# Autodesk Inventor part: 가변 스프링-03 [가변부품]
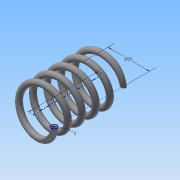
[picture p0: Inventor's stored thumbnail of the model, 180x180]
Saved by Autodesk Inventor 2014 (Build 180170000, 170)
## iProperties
Created: 2015-09
Part Number: 가변 스프링-03 [가변부품]
Material: 강철, 탄소
Document SubType Name: Modeling
Designer: study
Density: 7.87 g/cm^3
Appearance: 반연마
Mass: 18.8111 g
Surface Area: 32.4633 cm^2
Volume: 2.39023 cm^3
Author: study
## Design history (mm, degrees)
sketch "스케치1"
  geometry: L1 (0, 0)-(11, 0); L2 (11, 0)-(11, 28.893); L3 (11, 28.893)-(0, 28.893); L4 (0, 28.893)-(0, 0); C1 r 1.5 at (11, 0)
  constraints: 8 end point, 2 parallel, 1 centre point, 1 coincident, 1 horizontal, 1 perpendicular
  dimensions: "d0" = 22 diameter of L2.end L4; "d1" = 3 diameter of C1; "d2" = 28.89259 distance of L3.end L1.start (derived)
feature "코일1" sketch "스케치1" pitch "d3" = 10; turns "d5" = 5; dims "d4" = 28.89259 (= d2), "d6" = 0, angle "d7" = 90 deg, angle "d8" = 90 deg, "d9" = 0, "d10" = 0
node "작업 평면1"
sketch "스케치2"
  geometry: L1 (-12.5, 0)-(-9.5, 0) reference; 1 further point
  constraints: 1 horizontal alignment
extrude "돌출1" cut sketch "스케치2" stored distance "d12" = 10; taper "d13" = 0 deg
node "작업 평면2"
sketch "스케치3"
  geometry: L1 (-9.5, 0)-(-12.5, 0) reference; 1 further point
  constraints: 1 horizontal alignment
extrude "돌출2" cut sketch "스케치3" distance "d15" = 10; taper "d16" = 0 deg
node "솔리드1"
node "절단 모서리 투영1"
node "절단 모서리 투영2"
other parameters: "d11" = 0, "d14" = 28.89259 (= d2)
